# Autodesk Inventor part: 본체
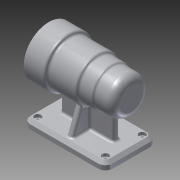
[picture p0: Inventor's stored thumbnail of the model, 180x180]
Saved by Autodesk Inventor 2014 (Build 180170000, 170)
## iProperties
Created: 2016-06
Part Number: 본체
Material: 알루미늄 6061
Document SubType Name: Modeling
Designer: SEC
Density: 2.71 g/cm^3
Appearance: 알루미늄 - 평지
Mass: 672.92 g
Surface Area: 647.114 cm^2
Volume: 248.31 cm^3
Author: SEC
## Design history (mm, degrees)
sketch "스케치1"
  geometry: L1 (-56, 35)-(56, 35); L2 (56, 35)-(56, -35); L3 (56, -35)-(-56, -35); L4 (-56, -35)-(-56, 35); 3 further points
  constraints: 8 end point, 2 midpoint, 2 parallel, 1 horizontal, 1 horizontal alignment, 1 perpendicular, 1 vertical alignment
  dimensions: "d0" = 70 distance between parallel lines of L3 L1; "d1" = 112 distance between parallel lines of L4 L2
extrude "돌출1" new body sketch "스케치1" distance "d2" = 10; taper "d3" = 0 deg
sketch "스케치3"
  geometry: L1 (-56, 35)-(-56, -35) reference; L2 (56, -35)-(56, 35) reference; L3 (-36, 4)-(36, 4); L4 (36, 4)-(36, -4); L5 (36, -4)-(-36, -4); L6 (-36, -4)-(-36, 4); 2 further points
  constraints: 8 end point, 2 parallel, 1 horizontal, 1 horizontal alignment, 1 midpoint, 1 perpendicular
  dimensions: "d4" = 8 distance between parallel lines of L5 L3; "d5" = 20 distance between parallel lines of L4 L2; "d6" = 20 distance between parallel lines of L1 L6
extrude "돌출2" join sketch "스케치3" distance "d7" = 70; taper "d8" = 0 deg
sketch "스케치4"
  geometry: L1 (35, 10)-(-35, 10) reference; L2 (4, 10)-(4, 80) reference; L3 (28, 10)-(4, 75.939); 1 further point
  constraints: 2 end point, 2 point on line
  dimensions: "d9" = 7 distance of L3.start L1.start; "d10" = 110 deg angle of L3 L1
feature "리브1" sketch "스케치4" dims "d11" = 1, "d12" = 8, "d13" = 0, "d14" = 0, "d15" = 1, "d16" = 1
node "작업 평면1"
sketch "스케치5"
  geometry: L1 (0, 70)-(0, 0) reference; C1 r 25 at (-70, 35); 2 further points
  constraints: 1 centre point, 1 horizontal alignment, 1 midpoint
  dimensions: "d17" = 70 distance of C1.centre point (0, 35); "d18" = 50 diameter of C1
extrude "돌출3" join sketch "스케치5" distance "d19" = 25; taper "d20" = 0 deg
sketch "스케치11"
  geometry: C1 r 27 at (70, 35); A1 r 25 centre (70, 35) between (45.322, 31) and (45.322, 39) reference; 1 further point
  constraints: 1 centre point, 1 coincident
  dimensions: "d34" = 54 diameter of C1
extrude "돌출8" join sketch "스케치11" distance "d35" = 20; taper "d36" = 0 deg
sketch "스케치12"
  geometry: C1 r 30 at (70, 35); A1 r 27 centre (70, 35) between (43.298, 31) and (43.298, 39) reference; 1 further point
  constraints: 1 centre point, 1 coincident
  dimensions: "d37" = 60 diameter of C1
extrude "돌출9" join sketch "스케치12" distance "d38" = 39; taper "d39" = 0 deg
sketch "스케치13"
  geometry: C1 r 34 at (70, 35); A1 r 30 centre (70, 35) between (40.268, 31) and (40.268, 39) reference; 1 further point
  constraints: 1 centre point, 1 coincident
  dimensions: "d40" = 68 diameter of C1
extrude "돌출10" join sketch "스케치13" distance "d41" = 28; taper "d42" = 0 deg
sketch "스케치14"
  geometry: 5 further points
  constraints: 1 horizontal alignment, 1 vertical alignment
  dimensions: "d43" = 46 horizontal distance of point (-46, -25) point (0, 0); "d44" = 25 vertical distance of point (-46, -25) point (0, 0); "d45" = 50 distance of point (-46, 25) point (-46, -25); "d46" = 92 distance of point (46, -25) point (-46, -25); "d47" = 50 distance of point (46, 25) point (46, -25); "d48" = 92 distance of point (-46, 25) point (46, 25)
hole "구멍1" sketch "스케치14" at (46, -25), (-46, -25), (-46, 25), (46, 25) diameter "d49" = 5; stored, may be unused: countersink angle "d53" = 90 deg, drill point angle "d55" = 118 deg; dims "d50" = 6, "d51" = 9, "d52" = 4, "d54" = 8
fillet "모깎기1" dims "d56" = 10
chamfer "모따기1" distance "d57" = 4; stored, may be unused: second distance "d58" = 2, angle "d59" = 45 deg
sketch "스케치15"
  geometry: C1 r 34 at (0, 0) reference; C2 r 21 at (0, 0); 1 further point
  constraints: 1 centre point, 1 coincident
  dimensions: "d60" = 42 diameter of C2
extrude "돌출11" cut sketch "스케치15" distance "d61" = 15; taper "d62" = 0 deg
sketch "스케치16"
  geometry: C1 r 21 at (0, 0) reference; C2 r 24 at (0, 0); 1 further point
  constraints: 1 centre point, 1 coincident
  dimensions: "d63" = 48 diameter of C2
extrude "돌출12" cut sketch "스케치16" distance "d64" = 54; taper "d65" = 0 deg
sketch "스케치17"
  geometry: C1 r 24 at (0, 0) reference; C2 r 21 at (0, 0); 1 further point
  constraints: 1 centre point, 1 coincident
  dimensions: "d66" = 42 diameter of C2
extrude "돌출13" cut sketch "스케치17" distance "d67" = 12; taper "d68" = 0 deg
sketch "스케치18"
  geometry: C1 r 21 at (0, 0) reference; C2 r 17.5 at (0, 0); 1 further point
  constraints: 1 centre point, 1 coincident
  dimensions: "d69" = 35 diameter of C2
extrude "돌출14" cut sketch "스케치18" distance "d70" = 18; taper "d71" = 0 deg
sketch "스케치19"
  geometry: C1 r 17.5 at (0, 0) reference; C2 r 16 at (0, 0); 1 further point
  constraints: 1 centre point, 1 coincident
  dimensions: "d72" = 32 diameter of C2
extrude "돌출15" cut sketch "스케치19" distance "d73" = 4; taper "d74" = 0 deg
sketch "스케치20"
  geometry: C1 r 16 at (0, 0) reference; C2 r 10.5 at (0, 0); 1 further point
  constraints: 1 centre point, 1 coincident
  dimensions: "d75" = 21 diameter of C2
extrude "돌출16" cut sketch "스케치20" distance "d76" = 3; taper "d77" = 0 deg
fillet "모깎기2" dims "d78" = 10
fillet "모깎기3" dims "d79" = 3
fillet "모깎기4" dims "d80" = 0.3
fillet "모깎기5" dims "d81" = 3
chamfer "모따기2" distance "d82" = 1; stored, may be unused: second distance "d83" = 2, angle "d84" = 45 deg
sketch "스케치21"
  geometry: C1 r 34 at (0, 0) reference; 2 further points
  constraints: 1 vertical alignment
  dimensions: "d85" = 26 distance of C1.centre point (0, 26)
hole "구멍2" sketch "스케치21" at (0, 26) diameter "d86" = 3.242; stored, may be unused: countersink angle "d90" = 90 deg, drill point angle "d92" = 118 deg; dims "d87" = 8, "d88" = 9, "d89" = 4, "d91" = 11
fillet "모깎기6" dims "d96" = 3
fillet "모깎기7" dims "d97" = 3
fillet "모깎기8" dims "d98" = 3
fillet "모깎기9" dims "d99" = 3
fillet "모깎기10" dims "d100" = 3
node "작업 평면2"
sketch "스케치22"
  geometry: L1 (56, 36)-(56, 104) reference; 2 further points
  constraints: 1 other
  dimensions: "d102" = 48 distance from line of point (8, 70) L1; "d103" = 70 vertical distance of point (8, 70) point (0, 0)
feature "엠보싱1" sketch "스케치22" dims "d104" = 0.5, "d105" = 0
node "솔리드1"
mirror "대칭1"
pattern_circular "원형 패턴1" dims angle "d94" = 360 deg
other parameters: "d101" = 43.25
